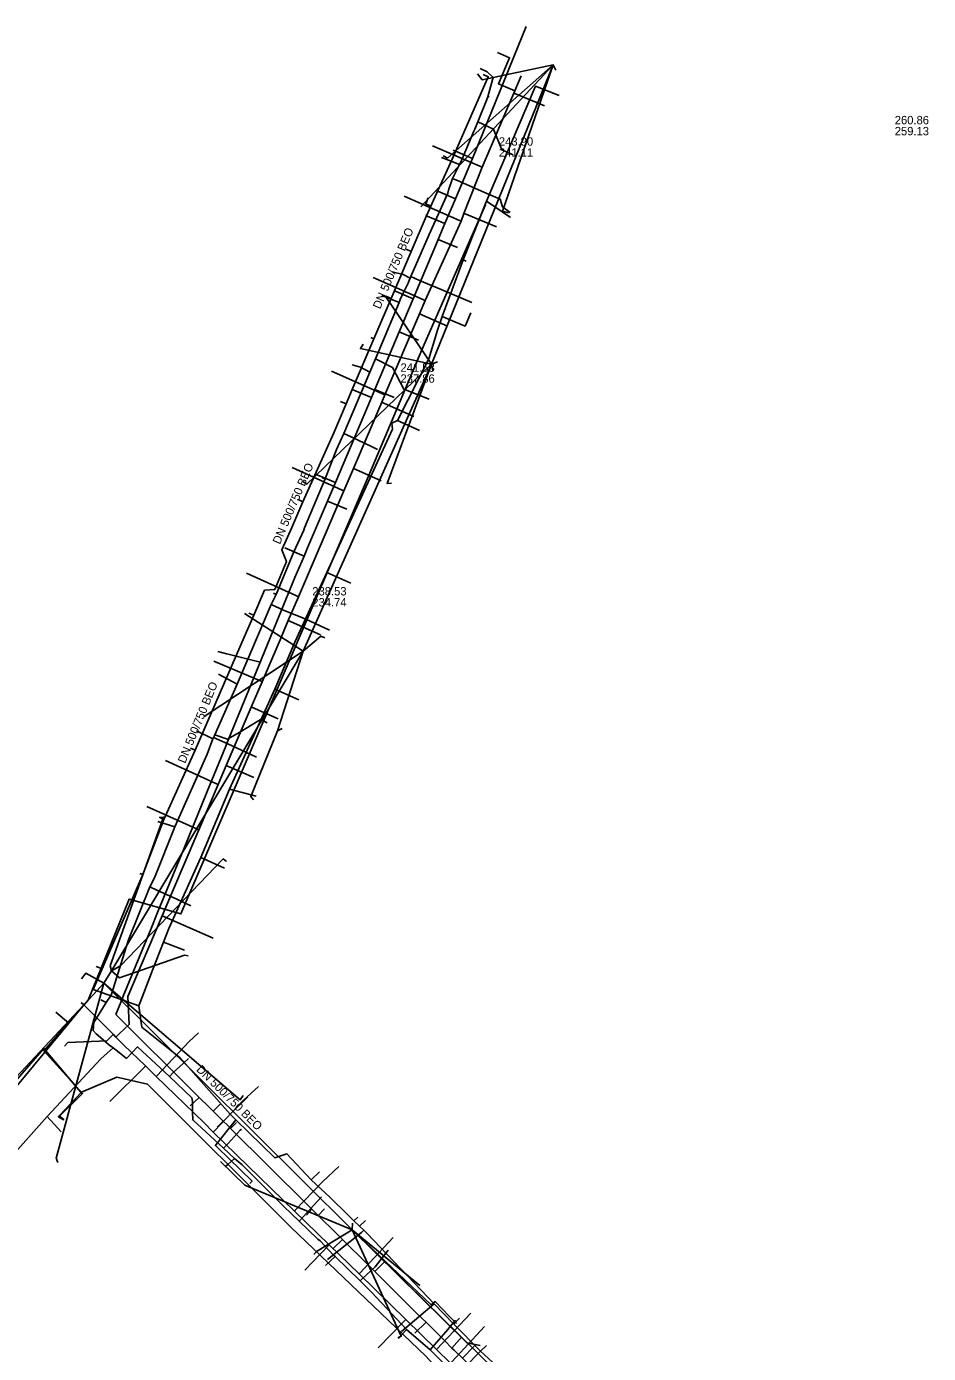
# Model space of a CAD drawing. Extents: x -598233 to -596890, y -1157848 to -1156431.
# Drawn here: x -597386.6 to -597300.5, y -1157384.6 to -1157257.8 of the extents above; entities that cross this region are included whole.
import ezdxf

# ---------------------------------------------------------------- set-up
doc = ezdxf.new("R2010")
doc.units = 0
for name, color, linetype in [('Vrstva 12', 7, 'Continuous'), ('Vrstva 13', 7, 'Continuous'), ('Vrstva 16', 7, 'Continuous'), ('Vrstva 4', 7, 'Continuous'), ('Vrstva 51', 7, 'Continuous'), ('Vrstva 55', 7, 'Continuous'), ('Vrstva 9', 7, 'Continuous')]:
    doc.layers.add(name, color=color, linetype=linetype)

msp = doc.modelspace()

# ---------------------------------------------------------------- linework, layer by layer
at = {"layer": 'Vrstva 12'}
for points in [[(-597343.03, -1157262.38), (-597342.54, -1157262.59), (-597345.99, -1157270.47), (-597347.76, -1157274.4), (-597348.01, -1157274.96)], [(-597335.75, -1157264.39), (-597338.03, -1157263.5), (-597342.7, -1157274.49)], [(-597348.01, -1157274.96), (-597348.5, -1157274.73), (-597348.26, -1157274.18)], [(-597348.01, -1157274.96), (-597348.56, -1157276.18), (-597349.89, -1157279.29)], [(-597342.7, -1157274.49), (-597344.92, -1157280.09)], [(-597342.7, -1157274.49), (-597340.42, -1157276.04)], [(-597349.89, -1157279.29), (-597351.82, -1157283.79)], [(-597349.89, -1157279.29), (-597350.37, -1157279.07)], [(-597344.92, -1157280.09), (-597346.95, -1157285.49)], [(-597344.92, -1157280.09), (-597344.64, -1157280.2)], [(-597351.82, -1157283.79), (-597353.48, -1157287.64)], [(-597351.82, -1157283.79), (-597352.32, -1157283.57)], [(-597346.95, -1157285.49), (-597347.4, -1157286.82), (-597348.21, -1157289.56), (-597351.2, -1157295.45)], [(-597346.95, -1157285.49), (-597344.74, -1157286.41), (-597344.21, -1157285.14)], [(-597353.48, -1157287.64), (-597355.54, -1157292.49)], [(-597353.48, -1157287.64), (-597353.75, -1157287.51)], [(-597355.54, -1157292.49), (-597356.12, -1157293.85)], [(-597356.12, -1157293.85), (-597357.3, -1157296.63), (-597360.23, -1157303.2)], [(-597356.12, -1157293.85), (-597356.65, -1157293.61)], [(-597351.2, -1157295.45), (-597351.75, -1157295.7), (-597351.69, -1157296.27), (-597354.89, -1157303.26)], [(-597349.11, -1157296.4), (-597351.2, -1157295.45)], [(-597360.23, -1157303.2), (-597361.31, -1157305.67), (-597362.25, -1157307.78), (-597361.81, -1157308.9), (-597362.93, -1157311.58), (-597363.89, -1157311.65), (-597364.93, -1157314.03)], [(-597360.23, -1157303.2), (-597360.7, -1157302.99)], [(-597354.89, -1157303.26), (-597357.95, -1157309.95)], [(-597357.95, -1157309.95), (-597361.02, -1157316.6), (-597362.92, -1157321.1)], [(-597357.95, -1157309.95), (-597355.67, -1157310.97)], [(-597364.93, -1157314.03), (-597365.84, -1157316.14)], [(-597364.93, -1157314.03), (-597365.39, -1157313.83)], [(-597365.84, -1157316.14), (-597370.52, -1157326.94)], [(-597362.92, -1157321.1), (-597367.24, -1157330.67)], [(-597362.92, -1157321.1), (-597360.64, -1157322.12)], [(-597370.52, -1157326.94), (-597373.52, -1157333.54)], [(-597370.52, -1157326.94), (-597370.96, -1157326.75)], [(-597367.24, -1157330.67), (-597369.99, -1157337.2)], [(-597367.24, -1157330.67), (-597364.71, -1157331.31)], [(-597373.52, -1157333.54), (-597375.53, -1157338.82)], [(-597373.52, -1157333.54), (-597373.84, -1157333.41)], [(-597369.99, -1157337.2), (-597373.03, -1157343.97), (-597373.54, -1157345.26)], [(-597369.99, -1157337.2), (-597367.71, -1157338.21)], [(-597375.53, -1157338.82), (-597379.41, -1157347.83)], [(-597375.53, -1157338.82), (-597375.81, -1157338.71)], [(-597373.54, -1157345.26), (-597374.59, -1157347.94)], [(-597371.54, -1157346.04), (-597373.54, -1157345.26)], [(-597375.92, -1157351.35), (-597380.27, -1157349.8), (-597379.41, -1157347.83)], [(-597379.41, -1157347.83), (-597379.97, -1157347.59)], [(-597374.69, -1157348.19), (-597375.92, -1157351.35)], [(-597374.59, -1157347.94), (-597374.69, -1157348.19)], [(-597375.92, -1157351.35), (-597375.62, -1157353.39), (-597371.97, -1157356.31), (-597367.18, -1157361.7)], [(-597367.18, -1157361.7), (-597365.49, -1157360.06)], [(-597367.18, -1157361.7), (-597366.65, -1157362.24)], [(-597366.65, -1157362.24), (-597368.53, -1157364.61)], [(-597366.65, -1157362.24), (-597362.91, -1157365.88), (-597361.77, -1157365.49), (-597359.44, -1157367.97)], [(-597368.53, -1157364.61), (-597368.6, -1157364.7), (-597368.43, -1157364.86)], [(-597368.43, -1157364.86), (-597365.09, -1157368.12), (-597365.3, -1157368.33)], [(-597359.44, -1157367.97), (-597358.64, -1157367.21)], [(-597359.44, -1157367.97), (-597357.62, -1157369.68), (-597355.94, -1157371.32), (-597355.39, -1157371.9)], [(-597355.39, -1157371.9), (-597354.99, -1157371.53)], [(-597355.39, -1157371.9), (-597354.83, -1157372.41)], [(-597354.83, -1157372.41), (-597354.25, -1157371.87)], [(-597357.88, -1157375.58), (-597354.63, -1157373), (-597354.42, -1157372.78)], [(-597354.83, -1157372.41), (-597354.42, -1157372.78)], [(-597354.42, -1157372.78), (-597354.11, -1157373.11)], [(-597354.11, -1157373.11), (-597347.69, -1157379.82)], [(-597347.69, -1157379.82), (-597350.82, -1157382.48)], [(-597347.69, -1157379.82), (-597345.84, -1157381.76)], [(-597345.84, -1157381.76), (-597345.27, -1157381.2)], [(-597345.84, -1157381.76), (-597343.27, -1157384.36)], [(-597343.27, -1157384.36), (-597342.7, -1157383.8)], [(-597343.27, -1157384.36), (-597341.75, -1157385.74)]]:
    msp.add_lwpolyline(points, dxfattribs=at)
at = {"layer": 'Vrstva 13'}
for p, q in [((-597343.11, -1157271.22), (-597347.87, -1157269.19)), ((-597348.56, -1157283.97), (-597353.53, -1157281.79)), ((-597349.11, -1157285.26), (-597346.42, -1157286.44)), ((-597352.42, -1157292.99), (-597357.51, -1157290.73)), ((-597361.63, -1157314.55), (-597358.57, -1157315.91)), ((-597381.15, -1157351.27), (-597381.4, -1157351.05)), ((-597381.15, -1157351.27), (-597381.28, -1157351.43)), ((-597382.59, -1157353.01), (-597383.83, -1157351.97)), ((-597377.77, -1157354.02), (-597378.09, -1157354.34)), ((-597377.33, -1157355.1), (-597378.09, -1157354.34)), ((-597357.73, -1157374.19), (-597360.06, -1157376.62)), ((-597347.47, -1157384.18), (-597344.2, -1157380.71))]:
    msp.add_line(p, q, dxfattribs=at)
for points in [[(-597339.99, -1157263.93), (-597341.57, -1157263.26), (-597340.5, -1157260.79), (-597341.64, -1157260.29)], [(-597377.77, -1157354.02), (-597376.84, -1157353.13), (-597376.97, -1157350.45), (-597373.68, -1157342.75), (-597371.77, -1157338.27), (-597370.18, -1157334.55), (-597368.33, -1157330.21), (-597367.55, -1157328.4), (-597365.17, -1157322.82), (-597364.12, -1157320.4), (-597362.42, -1157316.4), (-597361.63, -1157314.55), (-597360.66, -1157312.27), (-597356.33, -1157302.16), (-597355.42, -1157300.02), (-597352.71, -1157293.69), (-597352.42, -1157292.99), (-597349.11, -1157285.26), (-597348.56, -1157283.97), (-597345.14, -1157276.38), (-597344.88, -1157275.65), (-597343.11, -1157271.22), (-597340.09, -1157264.17), (-597339.99, -1157263.93), (-597339.38, -1157262.5)], [(-597340.09, -1157264.17), (-597340, -1157264.2), (-597337.16, -1157265.39)], [(-597345.14, -1157276.38), (-597345.29, -1157276.32), (-597350.58, -1157274.01)], [(-597344.88, -1157275.65), (-597344.59, -1157275.77), (-597341.76, -1157276.95)], [(-597352.71, -1157293.69), (-597352.46, -1157293.8), (-597349.63, -1157295.04)], [(-597356.33, -1157302.16), (-597356.49, -1157302.09), (-597361.27, -1157299.94)], [(-597355.42, -1157300.02), (-597355.18, -1157300.12), (-597352.75, -1157301.2)], [(-597360.66, -1157312.27), (-597360.91, -1157312.16), (-597365.63, -1157310.01)], [(-597364.12, -1157320.4), (-597364.23, -1157320.35), (-597368.75, -1157318.42)], [(-597365.17, -1157322.82), (-597365.06, -1157322.87), (-597362.6, -1157323.95)], [(-597368.33, -1157330.21), (-597368.55, -1157330.11), (-597373.36, -1157327.93)], [(-597367.55, -1157328.4), (-597367.49, -1157328.43), (-597367.28, -1157328.51), (-597364.91, -1157329.55)], [(-597370.18, -1157334.55), (-597370.28, -1157334.5), (-597370.47, -1157334.42), (-597375.14, -1157332.32)], [(-597373.68, -1157342.75), (-597373.44, -1157342.85), (-597368.81, -1157344.88)], [(-597381.28, -1157351.43), (-597382.59, -1157353.01), (-597401.96, -1157376.35), (-597402.95, -1157377.54)], [(-597378.09, -1157354.34), (-597378.34, -1157354.09), (-597381.15, -1157351.27)], [(-597378.34, -1157354.09), (-597378.38, -1157354.13), (-597378.96, -1157354.69), (-597382.68, -1157354.87), (-597383.01, -1157355.2)], [(-597374.24, -1157358.1), (-597374.18, -1157358.03), (-597371.1, -1157354.77), (-597370.22, -1157353.93)], [(-597310.24, -1157420.45), (-597312.28, -1157418.47), (-597318.96, -1157411.96), (-597325.11, -1157405.97), (-597328.54, -1157402.62), (-597338.81, -1157392.63), (-597340.33, -1157391.15), (-597343.73, -1157387.83), (-597346.14, -1157385.48), (-597347.47, -1157384.18), (-597350.42, -1157381.32), (-597354.88, -1157376.97), (-597357.73, -1157374.19), (-597361.04, -1157370.97), (-597368.8, -1157363.41), (-597369.69, -1157362.49), (-597374.24, -1157358.1), (-597375.27, -1157357.1), (-597377.33, -1157355.1)], [(-597375.27, -1157357.1), (-597375.31, -1157357.15), (-597378.67, -1157360.48)], [(-597368.8, -1157363.41), (-597368.65, -1157363.25), (-597365.95, -1157360.41), (-597364.48, -1157359.07)], [(-597361.04, -1157370.97), (-597361, -1157370.92), (-597358.38, -1157368.17), (-597356.81, -1157366.7)], [(-597354.88, -1157376.97), (-597354.8, -1157376.88), (-597351.63, -1157373.48)], [(-597350.42, -1157381.32), (-597350.51, -1157381.41), (-597353.06, -1157384.03)], [(-597346.14, -1157385.48), (-597346.03, -1157385.36), (-597342.9, -1157381.98)]]:
    msp.add_lwpolyline(points, dxfattribs=at)
at = {"layer": 'Vrstva 16'}
for points in [[(-597343.31, -1157261.82), (-597342.64, -1157262.13), (-597342.07, -1157262.66)], [(-597342.6, -1157264.61), (-597342.07, -1157262.66)], [(-597388.47, -1157366.24), (-597384.67, -1157361.94), (-597379.52, -1157356.41), (-597378.36, -1157355.38), (-597378.81, -1157355.06), (-597379.8, -1157354.18), (-597379.99, -1157354.04), (-597380.28, -1157353.72), (-597380.2, -1157352.95), (-597379.02, -1157351.04), (-597378.56, -1157350.35), (-597377.57, -1157347.17), (-597377.48, -1157346.88), (-597376.9, -1157345.05), (-597374.85, -1157339.99), (-597374.42, -1157339.14), (-597372.47, -1157334.24), (-597369.38, -1157327.3), (-597368.83, -1157325.85), (-597368.76, -1157325.71), (-597368.64, -1157325.47), (-597366.51, -1157320.61), (-597363.26, -1157313), (-597362.8, -1157312.05), (-597361.1, -1157307.98), (-597360.15, -1157305.91), (-597360.08, -1157305.7), (-597358.12, -1157301), (-597357.03, -1157298.2), (-597356.33, -1157296.69), (-597353.86, -1157290.82), (-597353.31, -1157289.54), (-597351.04, -1157284.15), (-597350.94, -1157283.87), (-597350.65, -1157283.26), (-597350.19, -1157282.31), (-597350.09, -1157282.05), (-597349.98, -1157281.83), (-597349.92, -1157281.69), (-597348.17, -1157277.68), (-597346.41, -1157273.72), (-597346.32, -1157273.43), (-597345.95, -1157272.33), (-597345.29, -1157270.97), (-597345.19, -1157270.81), (-597343.9, -1157267.81), (-597343.81, -1157267.59), (-597343.53, -1157266.89), (-597342.6, -1157264.61), (-597342.48, -1157264.43)], [(-597343.53, -1157266.89), (-597342.04, -1157267.6), (-597341.25, -1157269.58), (-597340.16, -1157270.07)], [(-597345.29, -1157270.97), (-597346.32, -1157270.57), (-597347, -1157270.31)], [(-597345.95, -1157272.33), (-597345.24, -1157272.62), (-597343.18, -1157273.54), (-597341.41, -1157274.29), (-597341.17, -1157275.04), (-597340.43, -1157275.58)], [(-597351.7, -1157281.24), (-597350.67, -1157281.48)], [(-597349.98, -1157281.83), (-597350.67, -1157281.48)], [(-597349.92, -1157281.69), (-597349.1, -1157282.05), (-597347.05, -1157282.91), (-597344.11, -1157284.17)], [(-597351.04, -1157284.15), (-597352.71, -1157283.5)], [(-597353.31, -1157289.54), (-597351.69, -1157290.37), (-597350.61, -1157292.44), (-597348.18, -1157293.4)], [(-597355.52, -1157290.12), (-597354.73, -1157290.35)], [(-597353.86, -1157290.82), (-597354.73, -1157290.35)], [(-597356.33, -1157296.69), (-597355.62, -1157297), (-597353.7, -1157297.91), (-597353.11, -1157298.2)], [(-597358.12, -1157301), (-597358.39, -1157300.9)], [(-597362.8, -1157312.05), (-597363.03, -1157311.93)], [(-597363.26, -1157313), (-597362.08, -1157313.57), (-597359.97, -1157314.42), (-597357.69, -1157315.46)], [(-597366.51, -1157320.61), (-597368.31, -1157319.66)], [(-597368.64, -1157325.47), (-597367.43, -1157325.89), (-597366.27, -1157325.21), (-597364.53, -1157324.17), (-597364.43, -1157324.1), (-597364.29, -1157324.01), (-597363.66, -1157324.32)], [(-597368.83, -1157325.85), (-597370.39, -1157325.08)], [(-597368.76, -1157325.71), (-597367.42, -1157326.34), (-597365.22, -1157327.35), (-597364.66, -1157327.59)], [(-597372.47, -1157334.24), (-597374.08, -1157333.73)], [(-597374.85, -1157339.99), (-597374.2, -1157340.29), (-597372.27, -1157341.15), (-597370.94, -1157341.8)], [(-597379.02, -1157351.04), (-597379.52, -1157350.78)], [(-597378.36, -1157355.38), (-597377.95, -1157355.68), (-597377.08, -1157356.4)], [(-597345.53, -1157386.76), (-597348.07, -1157384.23), (-597350.36, -1157382.29), (-597353.65, -1157378.73), (-597354.35, -1157378.05), (-597354.77, -1157377.64), (-597357.17, -1157375.31), (-597357.33, -1157375.16), (-597358.59, -1157373.81), (-597358.82, -1157373.64), (-597360.6, -1157371.94), (-597362.1, -1157370.5), (-597366.05, -1157366.55), (-597366.78, -1157365.93), (-597367.83, -1157364.94), (-597370.75, -1157362.26), (-597370.75, -1157361.98), (-597370.77, -1157361.73), (-597370.79, -1157360.48), (-597370.85, -1157360.16), (-597372.99, -1157358.1), (-597376.03, -1157355.28), (-597377.08, -1157356.4)], [(-597372.99, -1157358.1), (-597372.63, -1157357.73), (-597371.67, -1157356.85), (-597371.15, -1157356.38)], [(-597384.67, -1157361.94), (-597383.33, -1157363.39)], [(-597367.83, -1157364.94), (-597367.39, -1157364.5), (-597366.23, -1157363.24), (-597366.11, -1157363.13)], [(-597367.43, -1157366.54), (-597367.66, -1157366.72)], [(-597366.78, -1157365.93), (-597367.43, -1157366.54)], [(-597360.6, -1157371.94), (-597360.18, -1157371.48), (-597358.83, -1157370.02), (-597358.47, -1157369.59)], [(-597358.08, -1157376.16), (-597357.17, -1157375.31)], [(-597354.77, -1157377.64), (-597354.5, -1157377.36), (-597353.33, -1157376.29), (-597352.11, -1157374.71)], [(-597345.65, -1157381.39), (-597346.2, -1157382.03), (-597346.38, -1157382.24), (-597347.69, -1157383.77), (-597348.07, -1157384.23)], [(-597350.36, -1157382.29), (-597351.12, -1157383.15)], [(-597345.53, -1157386.76), (-597345.17, -1157386.32), (-597343.78, -1157384.87), (-597343, -1157384.06)]]:
    msp.add_lwpolyline(points, dxfattribs=at)
at = {"layer": 'Vrstva 51'}
for points in [[(-597336.33, -1157261.47), (-597336.33, -1157261.47), (-597348.99, -1157275.02)], [(-597336.33, -1157261.47), (-597347.96, -1157290.05)], [(-597336.33, -1157261.47), (-597336.33, -1157261.47), (-597346.42, -1157270.39)], [(-597336.33, -1157261.47), (-597336.33, -1157261.47), (-597343.13, -1157262.88), (-597343.55, -1157262.32)], [(-597336.33, -1157261.47), (-597336.33, -1157261.47), (-597341.17, -1157275.44), (-597340.61, -1157275.59)], [(-597336.33, -1157261.47), (-597336.07, -1157261.98)], [(-597346.42, -1157270.39), (-597346.83, -1157270.14)], [(-597347.96, -1157290.05), (-597352.31, -1157283.62)], [(-597347.96, -1157290.05), (-597354.75, -1157288.56), (-597354.48, -1157288.13)], [(-597347.96, -1157290.05), (-597347.96, -1157290.05), (-597359.86, -1157301.51), (-597360.26, -1157301.28)], [(-597347.96, -1157290.05), (-597360.21, -1157317.47)], [(-597347.96, -1157290.05), (-597347.96, -1157290.05), (-597352.2, -1157301.45), (-597351.78, -1157301.41)], [(-597347.96, -1157290.05), (-597347.39, -1157289.82)], [(-597347.96, -1157290.05), (-597347.96, -1157290.05), (-597347.83, -1157290.69)], [(-597360.21, -1157317.47), (-597365.83, -1157313.87)], [(-597360.21, -1157317.47), (-597358.52, -1157316.03), (-597358.13, -1157316.21)], [(-597360.21, -1157317.47), (-597378.53, -1157348.01), (-597379.24, -1157349.19)], [(-597360.21, -1157317.47), (-597369.67, -1157323.73)], [(-597360.21, -1157317.47), (-597362.66, -1157325.07)], [(-597362.66, -1157325.07), (-597362.21, -1157324.85)], [(-597362.66, -1157325.07), (-597365.22, -1157331.35), (-597364.96, -1157331.66)], [(-597378.53, -1157348.01), (-597378.64, -1157347.53), (-597373.55, -1157333.33), (-597373.97, -1157333.36)], [(-597378.53, -1157348.01), (-597377.66, -1157347.54), (-597367.84, -1157337.32), (-597367.54, -1157337.58)], [(-597378.53, -1157348.01), (-597377.74, -1157348.67), (-597371.54, -1157346.52), (-597371.2, -1157346.58)], [(-597379.24, -1157349.19), (-597380.96, -1157348.22), (-597381.38, -1157348.79)], [(-597379.24, -1157349.19), (-597380.28, -1157350.3), (-597399.23, -1157370.57), (-597400.01, -1157371.39), (-597400.32, -1157371.73)], [(-597379.24, -1157349.19), (-597383.8, -1157365.92), (-597383.64, -1157366.32)], [(-597379.24, -1157349.19), (-597366.22, -1157360.33), (-597365.93, -1157359.93)], [(-597379.24, -1157349.19), (-597355.53, -1157372.74)], [(-597355.53, -1157372.74), (-597365.79, -1157368.49), (-597368.11, -1157366.23)], [(-597355.53, -1157372.74), (-597358.95, -1157374.83), (-597359.18, -1157375.1)], [(-597355.53, -1157372.74), (-597355.5, -1157372.12)], [(-597355.53, -1157372.74), (-597350.84, -1157382.92), (-597351.16, -1157383.07)], [(-597355.53, -1157372.74), (-597349.06, -1157378.08)], [(-597355.53, -1157372.74), (-597347.99, -1157379.93), (-597347.62, -1157379.61), (-597346.26, -1157380.99), (-597345.57, -1157381.71)], [(-597355.53, -1157372.74), (-597344.59, -1157383.54), (-597343.31, -1157383.8)], [(-597355.53, -1157372.74), (-597329.8, -1157398)]]:
    msp.add_lwpolyline(points, dxfattribs=at)
at = {"layer": 'Vrstva 55'}
for points in [[(-597383.1, -1157362.26), (-597383.58, -1157361.95), (-597381.28, -1157359.72), (-597384.99, -1157355.64), (-597380.73, -1157350.81), (-597376.83, -1157341.16), (-597371.89, -1157342.57), (-597353.98, -1157300.76), (-597348.89, -1157288.69), (-597342.81, -1157274.82)], [(-597458.75, -1157297.73), (-597458.12, -1157297.25), (-597454.44, -1157302.35), (-597446.93, -1157314.01), (-597433.88, -1157333.37), (-597421.88, -1157351.08), (-597407.22, -1157374.62), (-597403.73, -1157372.24), (-597401.5, -1157372.41), (-597399.14, -1157371.72), (-597384.97, -1157355.43), (-597381.32, -1157359.76), (-597383.48, -1157361.88), (-597383.08, -1157362.21)], [(-597345.05, -1157454.85), (-597344.2, -1157454.54), (-597340.09, -1157460.44), (-597326.68, -1157449.71), (-597312.91, -1157439.52), (-597306.29, -1157434.51), (-597314.52, -1157424.86), (-597312.37, -1157421.82), (-597313.58, -1157419.18), (-597318.48, -1157414.2), (-597318.62, -1157414.38), (-597318.48, -1157414.2), (-597325.96, -1157406.62), (-597343.1, -1157390.75), (-597348.49, -1157384.81), (-597361.37, -1157372.54), (-597375.08, -1157358.84), (-597378, -1157358.16), (-597381.39, -1157359.59), (-597383.47, -1157361.84), (-597383.53, -1157362), (-597383.05, -1157362.21)]]:
    msp.add_lwpolyline(points, dxfattribs=at)
at = {"layer": 'Vrstva 9'}
for p, q in [((-597338.91, -1157257.8), (-597343.39, -1157268.84)), ((-597345.89, -1157269.62), (-597344.05, -1157270.4)), ((-597347.51, -1157273.47), (-597345.67, -1157274.25)), ((-597348.52, -1157275.86), (-597346.68, -1157276.63)), ((-597345.47, -1157278.92), (-597347.32, -1157278.14)), ((-597351.55, -1157283.02), (-597349.71, -1157283.8)), ((-597349.21, -1157287.76), (-597351.05, -1157286.98)), ((-597355.54, -1157292.46), (-597353.7, -1157293.24)), ((-597351.53, -1157293.25), (-597353.37, -1157292.47)), ((-597358.98, -1157300.58), (-597357.14, -1157301.36)), ((-597356.05, -1157303.91), (-597357.89, -1157303.13)), ((-597361.97, -1157307.61), (-597360.13, -1157308.39)), ((-597367.4, -1157317.76), (-597368.35, -1157317.51)), ((-597364.31, -1157318.53), (-597367.39, -1157317.77)), ((-597371.01, -1157360.92), (-597370.13, -1157360.12)), ((-597368.13, -1157360.75), (-597368.8, -1157361.43)), ((-597368.43, -1157362.96), (-597367.84, -1157362.38)), ((-597366.59, -1157362.51), (-597367.14, -1157363.07)), ((-597359.91, -1157371.34), (-597359.37, -1157370.79)), ((-597358.17, -1157370.75), (-597358.78, -1157371.37)), ((-597357.32, -1157374.51), (-597356.46, -1157373.67)), ((-597352.43, -1157375.81), (-597353.37, -1157376.74)), ((-597349.56, -1157382.64), (-597348.48, -1157381.58)), ((-597345.05, -1157382.99), (-597346, -1157384.05)), ((-597343.89, -1157383.88), (-597345.01, -1157385.02))]:
    msp.add_line(p, q, dxfattribs=at)
for points in [[(-597343.39, -1157268.84), (-597344.05, -1157270.4), (-597345.67, -1157274.25), (-597345.86, -1157274.7), (-597346.68, -1157276.63), (-597347.32, -1157278.14), (-597347.39, -1157278.32), (-597349.71, -1157283.8), (-597351.05, -1157286.98), (-597352.86, -1157291.26)], [(-597352.86, -1157291.26), (-597353.37, -1157292.47), (-597353.7, -1157293.24), (-597357.14, -1157301.36), (-597357.89, -1157303.13), (-597359.79, -1157307.61), (-597360.13, -1157308.39), (-597361, -1157310.44)], [(-597361, -1157310.44), (-597363.29, -1157316.03), (-597363.93, -1157317.59), (-597367.3, -1157325.82), (-597367.53, -1157326.37), (-597367.6, -1157326.55), (-597369.37, -1157330.87), (-597371.52, -1157336.12), (-597374.05, -1157342.29), (-597374.8, -1157344.12), (-597375.2, -1157345.1), (-597377.39, -1157350.44), (-597377.53, -1157350.78), (-597378.11, -1157352.19)], [(-597378.11, -1157352.19), (-597370.52, -1157359.73), (-597370.13, -1157360.12), (-597369.2, -1157361.04), (-597368.8, -1157361.43), (-597368.16, -1157362.07), (-597367.84, -1157362.38), (-597367.45, -1157362.77), (-597367.14, -1157363.07), (-597359.87, -1157370.29), (-597359.37, -1157370.79), (-597359.26, -1157370.9), (-597358.78, -1157371.37), (-597357.03, -1157373.11), (-597356.46, -1157373.67), (-597354.03, -1157376.08), (-597353.37, -1157376.74), (-597349.22, -1157380.86), (-597348.48, -1157381.58), (-597346.68, -1157383.37), (-597346, -1157384.05), (-597345.8, -1157384.24), (-597345.01, -1157385.02), (-597343.64, -1157386.38)]]:
    msp.add_lwpolyline(points, dxfattribs=at)

# ---------------------------------------------------------------- texts
at = {"layer": 'Vrstva 12'}
for s, p in [('243.90', (-597341.52, -1157269.18)), ('241.11', (-597341.52, -1157270.23)), ('241.58', (-597350.92, -1157290.78)), ('237.86', (-597350.92, -1157291.83)), ('238.53', (-597359.34, -1157312.15)), ('234.74', (-597359.34, -1157313.2))]:
    msp.add_text(s, height=0.8, dxfattribs=at).set_placement(p)
for rotation, p in [(67.0934, (-597352.86, -1157284.85)), (66.9788, (-597362.43, -1157307.32)), (67.7236, (-597371.48, -1157328.25)), (315.2414, (-597370.47, -1157357.5))]:
    msp.add_text('DN 500/750 BEO', height=0.8, rotation=rotation, dxfattribs=at).set_placement(p)
at = {"layer": 'Vrstva 4'}
for s, p in [('260.86', (-597303.72, -1157267.14)), ('259.13', (-597303.72, -1157268.19))]:
    msp.add_text(s, height=0.8, dxfattribs=at).set_placement(p)

doc.saveas('drawing.dxf')
